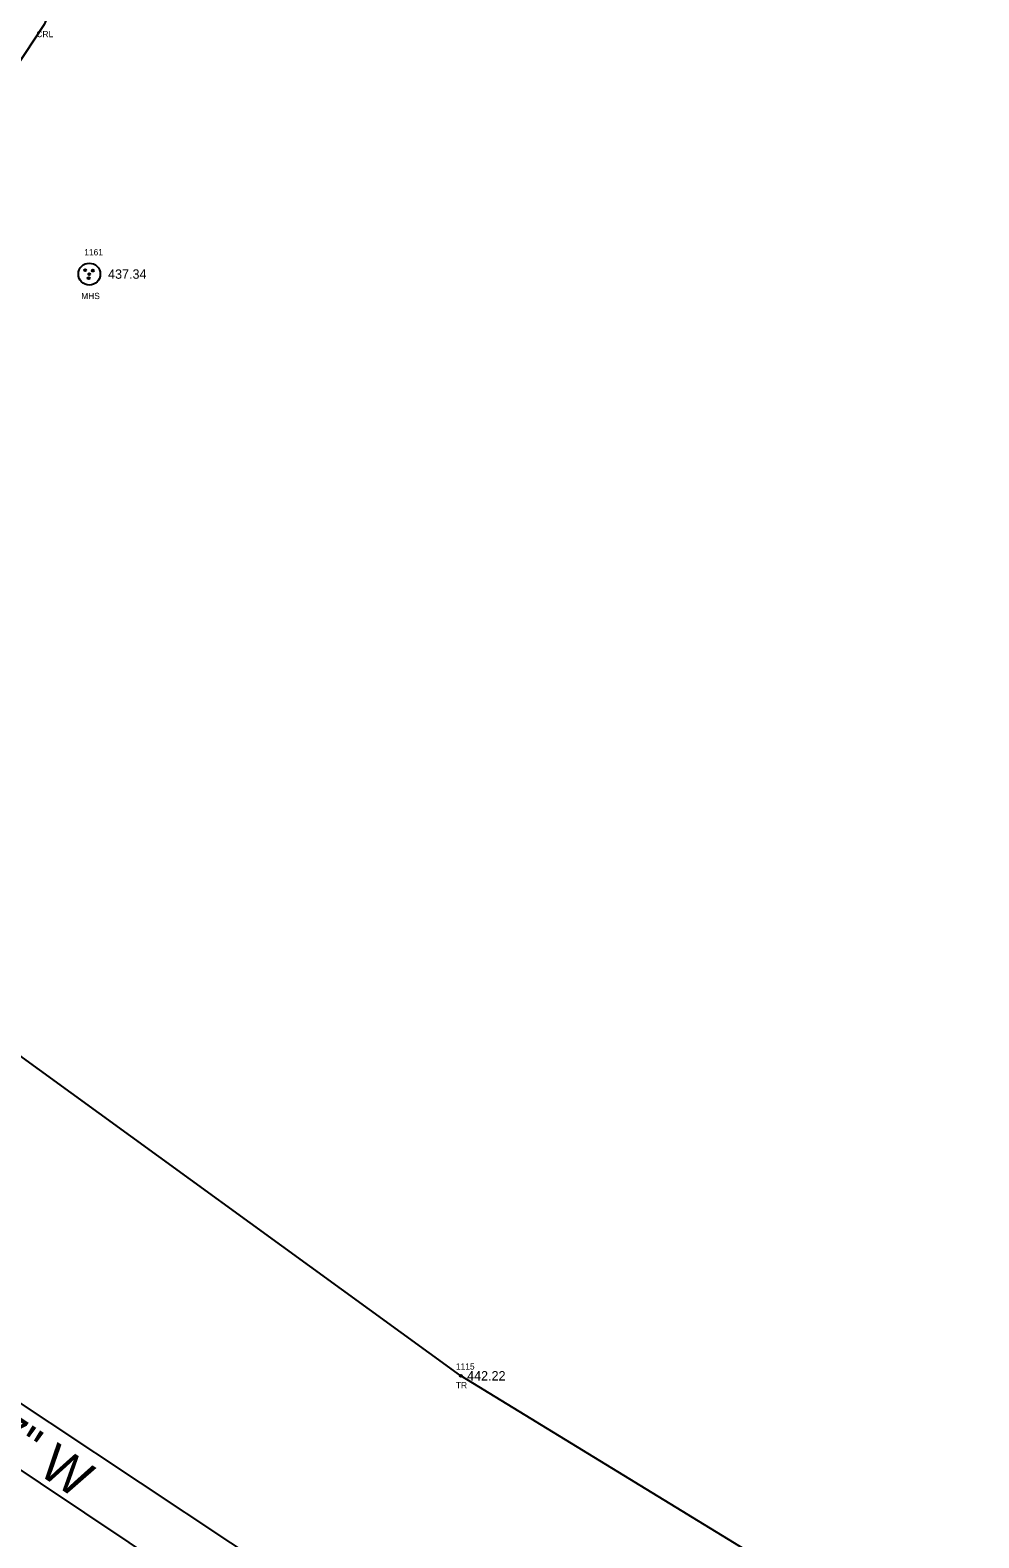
# Model space of a CAD drawing. Extents: x 1796360 to 1799195, y 895805 to 899730.
# Drawn here: x 1798527 to 1798678.6, y 896378.1 to 896619.1 of the extents above; entities that cross this region are included whole.
import ezdxf

# ---------------------------------------------------------------- set-up
doc = ezdxf.new("R2010")
doc.units = 0
for name, color, linetype in [('RD_EX_DR_Inlet', 7, 'Continuous'), ('RD_EX_H2O', 7, 'Continuous'), ('RD_EX_H2O_txCode', 7, 'Continuous'), ('RD_EX_Road', 7, 'Continuous'), ('RD_EX_TX_UT_ELEV', 7, 'Continuous'), ('RD_EX_TX_VEG_ELEV', 7, 'Continuous'), ('RD_EX_UT_txCode', 7, 'Continuous'), ('RD_EX_VEG', 7, 'Continuous'), ('RD_EX_VEG_txCode', 7, 'Continuous'), ('RD_HC_Cl', 7, 'Continuous'), ('RD_HC_Data', 7, 'Continuous'), ('RD_SMD_Locator', 7, 'Continuous')]:
    doc.layers.add(name, color=color, linetype=linetype)

msp = doc.modelspace()

# ---------------------------------------------------------------- linework, layer by layer
at = {"layer": 'RD_EX_DR_Inlet'}
for centre, radius in [((1798536.43, 896580.08), 1.75), ((1798535.77, 896580.71), 0.175), ((1798536.99, 896580.64), 0.175), ((1798536.34, 896579.42), 0.175)]:
    msp.add_circle(centre, radius, dxfattribs=at)
at = {"layer": 'RD_EX_H2O'}
msp.add_lwpolyline([(1798663.68, 896911.94), (1798617.01, 896821.94), (1798571.81, 896720.45), (1798529.2, 896619.95), (1798471.21, 896532.04), (1798459.45, 896520.86)], dxfattribs=at)
at = {"layer": 'RD_EX_Road'}
msp.add_lwpolyline([(1799016.83, 896078.37), (1798931.94, 896134.3), (1798843.73, 896191.67), (1798753.3, 896249.87), (1798664.51, 896307.9), (1798573.47, 896367.69), (1798486.82, 896425.22), (1798405.79, 896479.79), (1798400.67, 896472.53)], dxfattribs=at)
at = {"layer": 'RD_EX_VEG'}
msp.add_lwpolyline([(1799022.27, 896088.33), (1798937.86, 896144.41), (1798896.41, 896211.5), (1798869.11, 896228.04), (1798778.26, 896284.04), (1798691.36, 896345.52), (1798595.8, 896403.96), (1798518.88, 896459.81), (1798399.83, 896534.95), (1798299.84, 896602.99), (1798218.96, 896659.85), (1798132.31, 896718.94), (1798044.28, 896770.93), (1797952.52, 896827.83), (1797861.07, 896893.41), (1797773.58, 896947.34)], dxfattribs=at)
at = {"layer": 'RD_HC_Cl'}
msp.add_line((1798659.28, 896299.6), (1798362.69, 896497.51), dxfattribs=at)
at = {"layer": 'RD_SMD_Locator'}
for centre in [(1798536.43, 896580.08), (1798595.8, 896403.96)]:
    msp.add_circle(centre, 0.15, dxfattribs=at)

# ---------------------------------------------------------------- texts
at = {"layer": 'RD_EX_H2O_txCode'}
msp.add_text('CRL', height=1, dxfattribs=at).set_placement((1798527.98, 896617.95))
at = {"layer": 'RD_EX_TX_UT_ELEV'}
msp.add_text('437.34', height=1.5, dxfattribs=at).set_placement((1798539.43, 896579.33))
at = {"layer": 'RD_EX_TX_VEG_ELEV'}
msp.add_text('442.22', height=1.5, dxfattribs=at).set_placement((1798596.8, 896403.21))
at = {"layer": 'RD_EX_UT_txCode'}
for s, p in [('1161', (1798535.63, 896583.08)), ('MHS', (1798535.14, 896576.08))]:
    msp.add_text(s, height=1, dxfattribs=at).set_placement(p)
at = {"layer": 'RD_EX_VEG_txCode'}
for s, p in [('1115', (1798595.02, 896404.96)), ('TR', (1798595.01, 896401.96))]:
    msp.add_text(s, height=1, dxfattribs=at).set_placement(p)
at = {"layer": 'RD_HC_Data'}
msp.add_text('N 56%%d 17\' 07" W', height=6, rotation=326.2852, dxfattribs=at).set_placement((1798487.15, 896415.66))

doc.saveas('drawing.dxf')
